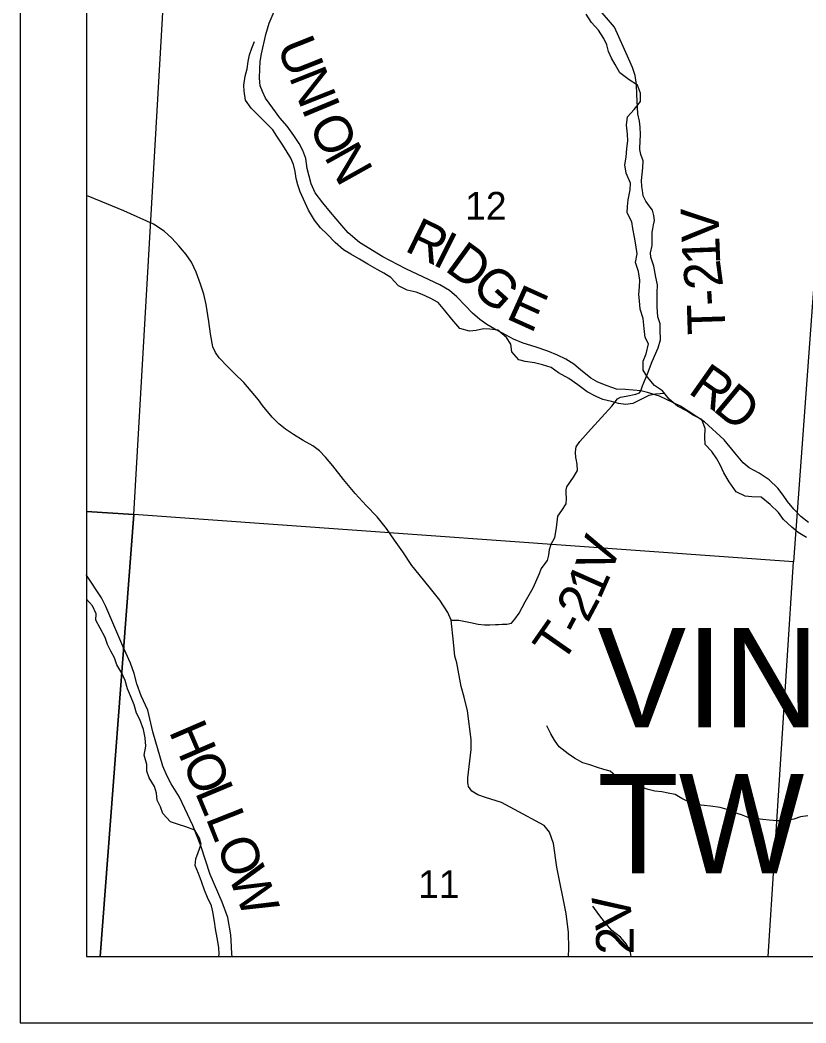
# Model space of a CAD drawing. Extents: x -8.2 to 34, y 0 to 22.
# Drawn here: x 2 to 3.185, y 14 to 15.511 of the extents above; entities that cross this region are included whole.
import ezdxf

# ---------------------------------------------------------------- set-up
doc = ezdxf.new("R2010")
doc.units = 0
for name, color, linetype in [('GM_X_Corporation', 7, 'Continuous'), ('GM_X_County_Road', 7, 'Continuous'), ('GM_X_County_Road_Text', 7, 'Continuous'), ('GM_X_Minor_River', 7, 'Continuous'), ('GM_X_Section_Text', 7, 'Continuous'), ('GM_X_Township_Road', 7, 'Continuous'), ('GM_X_Township_Road_Text', 7, 'Continuous'), ('GM_X_Township_Text', 7, 'Continuous'), ('SH_Data', 7, 'Continuous')]:
    doc.layers.add(name, color=color, linetype=linetype)

msp = doc.modelspace()

# ---------------------------------------------------------------- linework, layer by layer
at = {"layer": 'GM_X_Corporation'}
msp.add_lwpolyline([(2.1, 20.9), (2.1, 14.1), (4.1481, 14.1), (4.1604, 14.3288), (4.1741, 14.5315), (4.1846, 14.6878), (4.2113, 15.0848), (4.2352, 15.4906), (4.2558, 15.6585), (4.2674, 15.658), (4.2922, 15.6569), (4.4152, 15.6505), (4.4836, 15.6492), (5.4088, 15.5882), (6.2987, 15.5287), (6.3333, 15.9036), (6.368, 16.4128), (6.4323, 17.3579)], dxfattribs=at)
for points in [[(2.1, 15.7916), (2.1, 14.7705), (2.1717, 14.7662), (2.2302, 15.7835)], [(2.2302, 15.7835), (3.2411, 15.7231), (3.1659, 14.6948), (2.1717, 14.7662)], [(2.1, 14.7705), (2.1, 14.1), (2.1207, 14.1), (2.1717, 14.7662)], [(2.1207, 14.1), (3.1276, 14.1), (3.1659, 14.6948), (2.1717, 14.7662)]]:
    msp.add_lwpolyline(points, close=True, dxfattribs=at)
at = {"layer": 'GM_X_County_Road'}
msp.add_lwpolyline([(3.1887, 14.754), (3.1768, 14.763), (3.1666, 14.7739), (3.1567, 14.7857), (3.1503, 14.7952), (3.1421, 14.8056), (3.1294, 14.8183), (3.114, 14.828), (3.099, 14.8362), (3.0903, 14.8438), (3.0773, 14.8591), (3.0614, 14.8785), (3.0319, 14.9056), (2.9954, 14.9294), (2.9637, 14.9441), (2.9457, 14.9497), (2.9356, 14.9521), (2.9126, 14.9542), (2.8991, 14.9546), (2.8848, 14.96), (2.8708, 14.9653), (2.8604, 14.9715), (2.8446, 14.984), (2.8346, 14.9925), (2.8226, 15.0002), (2.8101, 15.006), (2.7956, 15.0118), (2.7767, 15.0187), (2.7585, 15.0243), (2.744, 15.0301), (2.7271, 15.0391), (2.7158, 15.0454), (2.7038, 15.052), (2.6929, 15.0598), (2.6818, 15.0694), (2.6709, 15.0807), (2.6586, 15.0937), (2.6475, 15.1032), (2.6328, 15.1119), (2.6081, 15.1237), (2.5814, 15.1361), (2.547, 15.1544), (2.5118, 15.1757), (2.4945, 15.1904), (2.4849, 15.2013), (2.4678, 15.2215), (2.4564, 15.2356), (2.4449, 15.2507), (2.4389, 15.2643), (2.4326, 15.287), (2.4306, 15.3025), (2.4262, 15.3145), (2.4207, 15.325), (2.4126, 15.337), (2.4026, 15.3508), (2.3915, 15.3637), (2.381, 15.3783), (2.3701, 15.393), (2.3655, 15.403), (2.3622, 15.4119), (2.361, 15.4233), (2.3613, 15.4373), (2.3621, 15.4484), (2.3639, 15.46), (2.3706, 15.4891), (2.3755, 15.506), (2.386, 15.5307)], dxfattribs=at)
at = {"layer": 'GM_X_Minor_River'}
for points in [[(2.944, 15.0078), (2.9474, 15.0229), (2.9425, 15.0324), (2.9409, 15.0464), (2.9394, 15.0612), (2.9348, 15.0753), (2.9337, 15.0881), (2.9329, 15.0976), (2.9337, 15.109), (2.9344, 15.1189), (2.9325, 15.1321), (2.9279, 15.1458), (2.9302, 15.1587), (2.9283, 15.1723), (2.9264, 15.184), (2.9237, 15.1969), (2.9222, 15.2068), (2.9153, 15.2204), (2.9157, 15.2299), (2.9165, 15.2398), (2.9195, 15.2553), (2.9202, 15.2652), (2.9138, 15.28), (2.9119, 15.2928), (2.9137, 15.3042), (2.9145, 15.3175), (2.916, 15.3289), (2.9156, 15.3391), (2.9144, 15.3524), (2.9156, 15.3653), (2.9258, 15.3759), (2.9352, 15.388), (2.9352, 15.4006), (2.931, 15.4127), (2.9181, 15.421), (2.9041, 15.4316), (2.8969, 15.4437), (2.8916, 15.4532), (2.887, 15.4634), (2.8844, 15.4737), (2.8802, 15.4831), (2.8722, 15.4956), (2.8612, 15.507), (2.8536, 15.5195)], [(2.9718, 14.9481), (2.9581, 14.9475), (2.9479, 14.9452), (2.9369, 14.9395), (2.9236, 14.9334), (2.9134, 14.9315), (2.9021, 14.9334), (2.8914, 14.9361), (2.8786, 14.9394), (2.8687, 14.9436), (2.8547, 14.9508), (2.841, 14.9614), (2.8274, 14.9708), (2.8115, 14.9795), (2.8008, 14.9875), (2.7876, 14.9913), (2.7755, 14.9943), (2.7614, 14.9965), (2.752, 14.9988), (2.7413, 15.0109), (2.7398, 15.0226), (2.7334, 15.0325), (2.7201, 15.0435), (2.7084, 15.0454), (2.6985, 15.0457), (2.6875, 15.043), (2.6777, 15.0423), (2.6629, 15.0464), (2.6511, 15.0604), (2.6405, 15.0733), (2.6303, 15.0854), (2.6181, 15.0919), (2.6064, 15.0975), (2.5969, 15.1009), (2.5837, 15.1039), (2.5704, 15.1107), (2.559, 15.1229), (2.5484, 15.1293), (2.5385, 15.1353), (2.5245, 15.1429), (2.5116, 15.1508), (2.4984, 15.158), (2.4874, 15.1648), (2.4752, 15.1758), (2.4631, 15.1883), (2.4529, 15.1978), (2.4441, 15.2095), (2.435, 15.2243), (2.4221, 15.2523), (2.4187, 15.2626), (2.4164, 15.2724), (2.4145, 15.2826), (2.4122, 15.2933), (2.408, 15.3027), (2.4012, 15.3145), (2.3951, 15.3239), (2.3872, 15.3361), (2.3811, 15.3455), (2.3693, 15.3569), (2.3595, 15.3671), (2.3485, 15.3781), (2.3398, 15.3902), (2.3378, 15.4035), (2.3375, 15.413), (2.3393, 15.4262), (2.3423, 15.4376), (2.3438, 15.4486), (2.3457, 15.4585), (2.3495, 15.4687), (2.3533, 15.4786)], [(3.1853, 14.7314), (3.1731, 14.7389), (3.1636, 14.7469), (3.1507, 14.7582), (3.1432, 14.7688), (3.1306, 14.781), (3.117, 14.7919), (3.103, 14.7927), (3.0931, 14.7938), (3.0795, 14.8002), (3.0689, 14.8154), (3.0609, 14.8286), (3.056, 14.84), (3.0506, 14.8498), (3.0427, 14.8608), (3.0328, 14.8714), (3.0324, 14.8828), (3.0328, 14.8957), (3.0275, 14.909), (3.0146, 14.9158), (3.0047, 14.9222), (2.9911, 14.9294), (2.9786, 14.9396), (2.9687, 14.9521), (2.9566, 14.9604), (2.9456, 14.9729), (2.9395, 14.9835), (2.9395, 14.9968), (2.944, 15.0078)], [(2.2692, 14.2251), (2.2642, 14.2373), (2.265, 14.2471), (2.2684, 14.2566), (2.2729, 14.2691), (2.2706, 14.2786), (2.2634, 14.2903), (2.2501, 14.2956), (2.2391, 14.299), (2.2266, 14.3028), (2.2153, 14.3153), (2.2115, 14.3255), (2.2065, 14.3354), (2.2058, 14.3464), (2.2027, 14.3562), (2.1944, 14.3691), (2.1913, 14.3793), (2.1909, 14.3892), (2.1871, 14.4032), (2.1898, 14.4172), (2.1886, 14.4293), (2.1859, 14.4422), (2.1806, 14.457), (2.1753, 14.4665), (2.1719, 14.479), (2.1666, 14.4926), (2.162, 14.5032), (2.1586, 14.5157), (2.1536, 14.5267), (2.1461, 14.5396), (2.1423, 14.5502), (2.1369, 14.5601), (2.132, 14.5699), (2.1282, 14.5805), (2.1206, 14.5945), (2.1142, 14.6066), (2.1145, 14.6165), (2.1092, 14.6282), (2.1, 14.6385)], [(3.1876, 14.3121), (3.1767, 14.3106), (3.1664, 14.3071), (3.1551, 14.3045), (3.1414, 14.3044), (3.1293, 14.3056), (3.1195, 14.3063), (3.1077, 14.3082), (3.0975, 14.3093), (3.0876, 14.3135), (3.0759, 14.3169), (3.0657, 14.3214), (3.0554, 14.3244), (3.0406, 14.3267), (3.0312, 14.3278), (3.0175, 14.3293), (3.0077, 14.3331), (2.9978, 14.338), (2.9876, 14.344), (2.977, 14.3463), (2.9675, 14.3482), (2.9569, 14.3493), (2.9467, 14.3519), (2.9368, 14.355), (2.9236, 14.3621), (2.9133, 14.3667), (2.9012, 14.3693), (2.8894, 14.3795), (2.88, 14.3818), (2.8705, 14.3848), (2.8588, 14.389), (2.8485, 14.392), (2.836, 14.3988), (2.8262, 14.4056), (2.8129, 14.4162), (2.8057, 14.426), (2.8, 14.4355), (2.7939, 14.4476)], [(2.2995, 14.1), (2.3, 14.1035), (2.2996, 14.1137), (2.2973, 14.1281), (2.2946, 14.1418), (2.2931, 14.1528), (2.2904, 14.1672), (2.2885, 14.1766), (2.2825, 14.1891), (2.2783, 14.1998), (2.2733, 14.213), (2.2692, 14.2251)], [(2.9212, 14.1), (2.9201, 14.1059), (2.914, 14.1187), (2.9053, 14.1293), (2.892, 14.1392), (2.8825, 14.1505), (2.8727, 14.1634), (2.8632, 14.1759)]]:
    msp.add_lwpolyline(points, dxfattribs=at)
at = {"layer": 'GM_X_Township_Road'}
for points in [[(2.9342, 15.3183), (2.9346, 15.3278), (2.9353, 15.3386), (2.9348, 15.3497), (2.934, 15.3586), (2.9312, 15.3698), (2.9296, 15.3988), (2.9294, 15.4136), (2.9272, 15.4272), (2.9231, 15.4394), (2.9175, 15.4518), (2.8963, 15.4999), (2.8497, 15.5545)], [(2.9356, 14.9521), (2.9382, 14.9596), (2.9459, 14.9779), (2.9531, 14.9963), (2.9618, 15.0172), (2.9652, 15.0293), (2.9649, 15.0447), (2.9647, 15.0533), (2.9615, 15.0638), (2.9605, 15.0787), (2.9605, 15.0998), (2.9611, 15.1121), (2.9586, 15.1236), (2.9553, 15.14), (2.9511, 15.1537), (2.9506, 15.16), (2.9527, 15.1712), (2.9531, 15.1827), (2.9531, 15.1912), (2.9539, 15.1961), (2.955, 15.2022), (2.9564, 15.2087), (2.9556, 15.2163), (2.9534, 15.2247), (2.9484, 15.231), (2.9432, 15.238), (2.9391, 15.2462), (2.9382, 15.2542), (2.9372, 15.2603), (2.9369, 15.2689), (2.9388, 15.2884), (2.9391, 15.2988), (2.9357, 15.3085), (2.9341, 15.3159), (2.9342, 15.3183)], [(2.6757, 14.359), (2.6752, 14.3619), (2.6748, 14.3694), (2.6798, 14.412), (2.6798, 14.427), (2.6747, 14.4701), (2.6697, 14.4906), (2.6651, 14.5069), (2.6584, 14.5423), (2.6556, 14.5525), (2.6534, 14.5738), (2.65, 14.6069), (2.6449, 14.6183), (2.633, 14.6368), (2.6208, 14.6519), (2.6082, 14.6675), (2.5908, 14.6891), (2.5768, 14.7097), (2.5643, 14.7275), (2.5525, 14.7451), (2.5385, 14.7623), (2.5219, 14.7794), (2.5051, 14.7976), (2.4878, 14.8185), (2.4713, 14.8392), (2.4605, 14.8523), (2.4516, 14.8621), (2.4416, 14.8694), (2.4267, 14.8775), (2.4122, 14.8864), (2.4, 14.8946), (2.3902, 14.9024), (2.3799, 14.9126), (2.3653, 14.93), (2.3595, 14.9389), (2.3372, 14.9646), (2.3234, 14.9782), (2.3125, 14.9889), (2.3003, 15.0022), (2.2947, 15.0102), (2.2907, 15.0185), (2.287, 15.0381), (2.2845, 15.0569), (2.2807, 15.0823), (2.2769, 15.0979), (2.2721, 15.1128), (2.2656, 15.131), (2.2583, 15.1459), (2.2505, 15.1577), (2.2396, 15.1708), (2.2289, 15.1822), (2.2171, 15.1928), (2.2011, 15.2035), (2.1564, 15.2235), (2.1222, 15.2376), (2.1, 15.2464)], [(2.8382, 14.8497), (2.838, 14.8508), (2.8375, 14.8604), (2.8383, 14.8679), (2.8439, 14.8758), (2.8525, 14.8857), (2.861, 14.8952), (2.892, 14.9293), (2.9006, 14.94), (2.9051, 14.9428), (2.9135, 14.9442), (2.9281, 14.9475), (2.9336, 14.9492), (2.9356, 14.9521)], [(2.65, 14.6069), (2.6615, 14.6066), (2.6788, 14.6033), (2.6905, 14.601), (2.7002, 14.5997), (2.7082, 14.5997), (2.7165, 14.6003), (2.7211, 14.6005), (2.727, 14.6008), (2.7337, 14.6007), (2.7408, 14.6025), (2.7457, 14.6082), (2.7523, 14.6174), (2.7612, 14.6346), (2.7735, 14.6554), (2.7832, 14.6771), (2.7857, 14.6842), (2.7951, 14.6967), (2.7972, 14.7046), (2.798, 14.7133), (2.8007, 14.7214), (2.8061, 14.7313), (2.8086, 14.7457), (2.8109, 14.7633), (2.8169, 14.7722), (2.823, 14.7821), (2.8235, 14.7901), (2.823, 14.7985), (2.8234, 14.8031), (2.8243, 14.8076), (2.8345, 14.8222), (2.8403, 14.8322), (2.8398, 14.8419), (2.8382, 14.8497)], [(2.3196, 14.1), (2.3192, 14.1037), (2.3189, 14.1152), (2.3175, 14.1329), (2.313, 14.1589), (2.3048, 14.1821), (2.2868, 14.2237), (2.2725, 14.2666), (2.2604, 14.2976), (2.2402, 14.3399), (2.2276, 14.3602), (2.2218, 14.3717), (2.2154, 14.3868), (2.2001, 14.4386), (2.1927, 14.4714), (2.1827, 14.4927), (2.176, 14.5108), (2.1722, 14.5264), (2.1665, 14.5422), (2.1547, 14.5674), (2.1293, 14.6273), (2.1226, 14.6406), (2.1002, 14.6748), (2.1, 14.6751)], [(2.8266, 14.1), (2.8275, 14.1119), (2.8268, 14.1362), (2.8234, 14.1647), (2.8092, 14.2347), (2.8043, 14.2704), (2.7982, 14.2874), (2.79, 14.2974), (2.7456, 14.3214), (2.726, 14.3321), (2.7018, 14.3395), (2.6901, 14.3436), (2.6811, 14.3494), (2.6762, 14.3561), (2.6757, 14.359)]]:
    msp.add_lwpolyline(points, dxfattribs=at)
at = {"layer": 'SH_Data'}
for p, q in [((2, 21), (2, 14)), ((2.1, 20.9), (2.1, 14.1)), ((2.1, 14.1), (2.1, 14.1)), ((2.1, 14.1), (4.1481, 14.1)), ((2, 14), (9, 14))]:
    msp.add_line(p, q, dxfattribs=at)

# ---------------------------------------------------------------- texts
at = {"layer": 'GM_X_County_Road_Text'}
for s, rotation, p in [('U', 291.5674, (2.3865, 15.4721)), ('N', 291.6163, (2.4049, 15.4256)), ('I', 292.5335, (2.4237, 15.3782)), ('O', 295.873, (2.4341, 15.3533)), ('N', 299.1158, (2.4575, 15.3052)), ('R', 333.9621, (2.578, 15.164)), ('I', 333.3721, (2.6197, 15.1436)), ('D', 323.8572, (2.6385, 15.1345)), ('G', 317.9299, (2.6777, 15.106)), ('E', 335.7341, (2.7308, 15.0619)), ('R', 324.8603, (3.0054, 14.9501)), ('D', 320.2439, (3.0426, 14.924))]:
    msp.add_text(s, height=0.0568, rotation=rotation, dxfattribs=at).set_placement(p)
at = {"layer": 'GM_X_Section_Text'}
for s, p in [('12', (2.6711, 15.2101)), ('11', (2.6002, 14.1881))]:
    msp.add_text(s, height=0.04186, rotation=0, dxfattribs=at).set_placement(p)
at = {"layer": 'GM_X_Township_Road_Text'}
for s, rotation, p in [('V', 91.9675, (3.0543, 15.1779)), ('1', 92.2904, (3.0557, 15.1431)), ('2', 97.6572, (3.0602, 15.1098)), ('-', 93.2943, (3.062, 15.0818)), ('T', 91.8346, (3.0634, 15.0377)), ('V', 70.361, (2.8899, 14.6725)), ('1', 66.1704, (2.8741, 14.6363)), ('2', 61.971, (2.8557, 14.6013)), ('-', 62.2182, (2.8448, 14.5807)), ('T', 55.0761, (2.8165, 14.5393)), ('H', 293.3263, (2.2237, 14.4394)), ('O', 293.31, (2.2435, 14.3935)), ('L', 292.7118, (2.2632, 14.3477)), ('L', 291.5754, (2.2795, 14.3088)), ('O', 290.834, (2.2951, 14.2695)), ('W', 291.34, (2.3131, 14.2222)), ('V', 97.6798, (2.9245, 14.1459)), ('2', 90.281, (2.9252, 14.1029))]:
    msp.add_text(s, height=0.0568, rotation=rotation, dxfattribs=at).set_placement(p)
at = {"layer": 'GM_X_Township_Text'}
for s, p in [('VINTON', (2.8704, 14.4452)), ('TWP.', (2.8704, 14.2252))]:
    msp.add_text(s, height=0.15, rotation=0, dxfattribs=at).set_placement(p)

doc.saveas('drawing.dxf')
